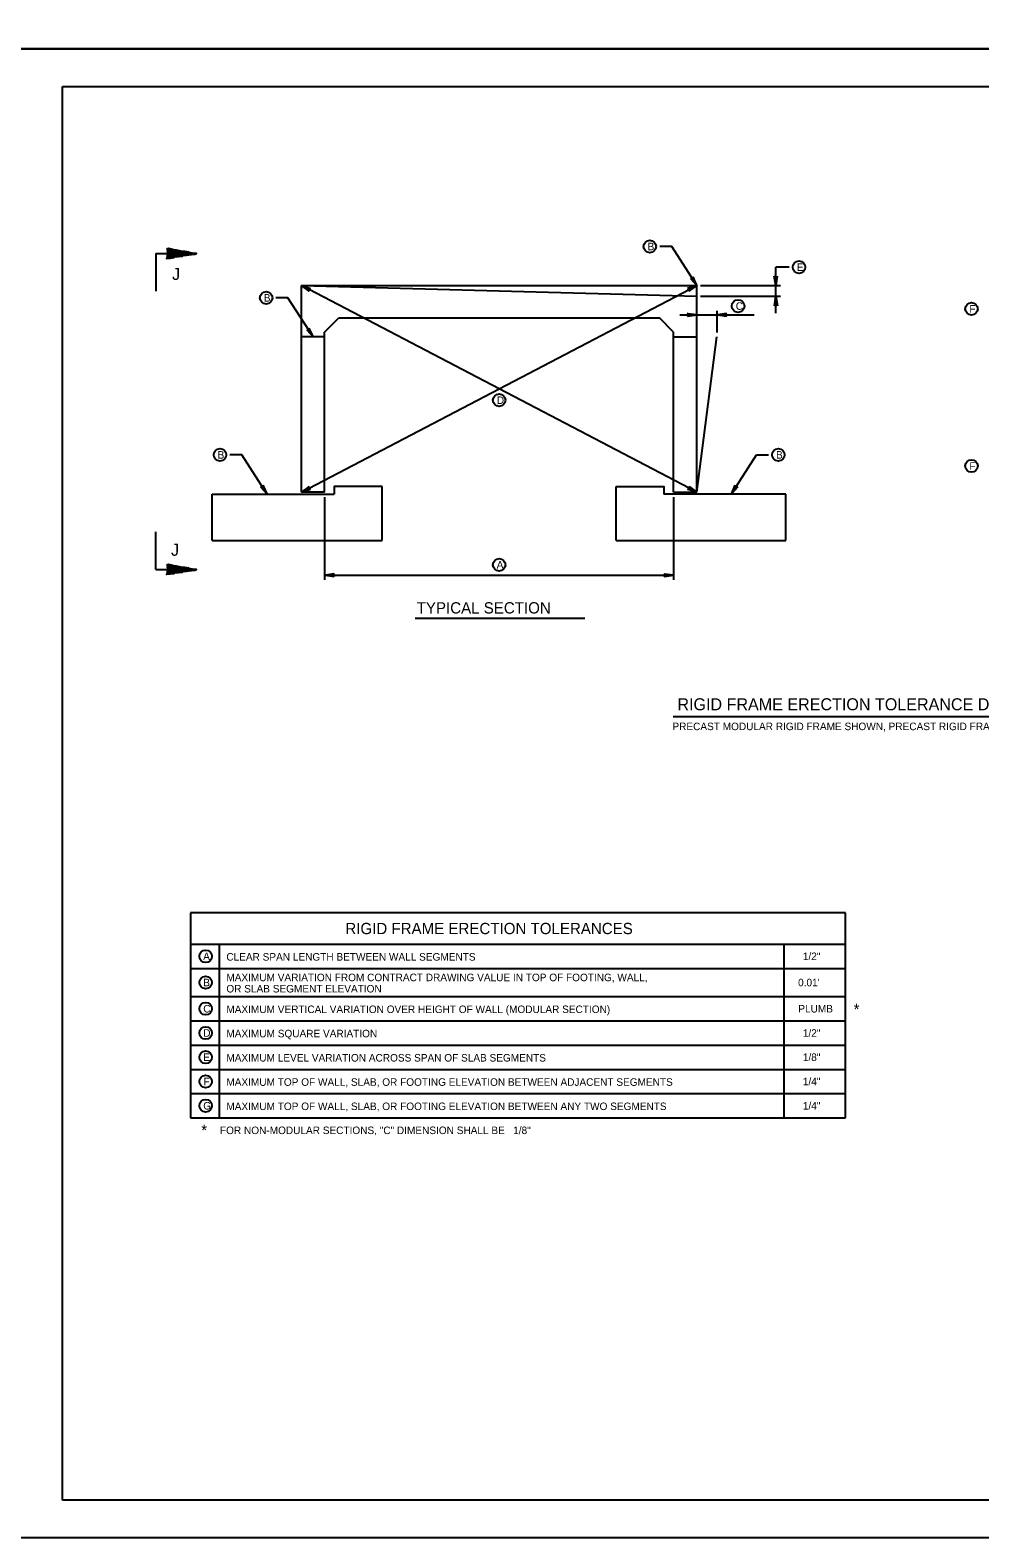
# Model space of a CAD drawing. Extents: x 641328 to 643024, y 298283 to 300065.
# Drawn here: x 642196 to 642575, y 298283 to 298885 of the extents above; entities that cross this region are included whole.
import ezdxf

# ---------------------------------------------------------------- set-up
doc = ezdxf.new("R2010")
doc.units = 0
doc.layers.add('2', color=7, linetype='Continuous')
doc.layers.add('PLT-BNDY', color=7, linetype='Continuous')

msp = doc.modelspace()

# ---------------------------------------------------------------- linework, layer by layer
at = {"layer": '2'}
for p, q in [((642208.51, 298298.3), (642208.51, 298862.3)), ((642208.51, 298862.3), (642994.5, 298862.3)), ((642245.76, 298795.71), (642245.76, 298780.68)), ((642245.76, 298795.71), (642260.79, 298795.71)), ((642451.59, 298798.49), (642446.77, 298798.49)), ((642461.6, 298782.89), (642451.59, 298798.49)), ((642493.12, 298771.84), (642493.12, 298790.22)), ((642498.42, 298790.22), (642493.12, 298790.22)), ((642459.29, 298785.69), (642459.05, 298785.77)), ((642459.05, 298785.77), (642461.6, 298782.89)), ((642459.29, 298785.69), (642459.59, 298785.72)), ((642461.6, 298782.89), (642459.29, 298785.69)), ((642459.59, 298785.72), (642459.89, 298785.91)), ((642459.59, 298785.72), (642461.6, 298782.89)), ((642461.6, 298782.89), (642459.74, 298785.82)), ((642459.89, 298785.91), (642460.04, 298786.16)), ((642461.6, 298782.89), (642459.89, 298785.91)), ((642460.09, 298786.42), (642460.04, 298786.16)), ((642460.04, 298786.16), (642461.6, 298782.89)), ((642461.6, 298782.89), (642460.09, 298786.42)), ((642493.12, 298782.89), (642492.49, 298786.68)), ((642492.49, 298786.68), (642492.66, 298786.48)), ((642492.92, 298786.36), (642492.66, 298786.48)), ((642492.66, 298786.48), (642493.12, 298782.89)), ((642493.12, 298782.89), (642492.92, 298786.36)), ((642493.29, 298786.36), (642492.92, 298786.36)), ((642493.12, 298782.89), (642493.1, 298786.36)), ((642493.71, 298786.69), (642493.12, 298782.89)), ((642493.12, 298782.89), (642493.55, 298786.5)), ((642493.29, 298786.36), (642493.12, 298782.89)), ((642493.55, 298786.5), (642493.29, 298786.36)), ((642493.55, 298786.5), (642493.71, 298786.69)), ((642298.49, 298777.99), (642293.67, 298777.99)), ((642308.5, 298762.39), (642298.49, 298777.99)), ((642303.85, 298782.89), (642461.6, 298782.89)), ((642303.85, 298700.46), (642303.85, 298782.89)), ((642303.85, 298700.46), (642461.6, 298782.89)), ((642461.6, 298700.46), (642303.85, 298782.89)), ((642306.85, 298781.13), (642303.85, 298782.89)), ((642303.85, 298782.89), (642306.85, 298780.83)), ((642306.95, 298780.6), (642303.85, 298782.89)), ((642303.85, 298782.89), (642307.02, 298781.45)), ((642307.25, 298781.63), (642303.85, 298782.89)), ((642303.85, 298782.89), (642307.51, 298781.69)), ((642303.85, 298782.89), (642306.94, 298781.29)), ((642303.85, 298782.89), (642461.6, 298778.63)), ((642306.85, 298781.13), (642307.02, 298781.45)), ((642306.85, 298780.83), (642306.85, 298781.13)), ((642306.85, 298780.83), (642306.95, 298780.6)), ((642307.02, 298781.45), (642307.25, 298781.63)), ((642307.51, 298781.69), (642307.25, 298781.63)), ((642461.6, 298782.89), (642457.94, 298781.69)), ((642457.94, 298781.69), (642458.2, 298781.63)), ((642458.2, 298781.63), (642461.6, 298782.89)), ((642458.43, 298781.45), (642458.2, 298781.63)), ((642461.6, 298782.89), (642458.43, 298781.45)), ((642458.6, 298781.13), (642458.43, 298781.45)), ((642458.5, 298780.6), (642461.6, 298782.89)), ((642458.6, 298780.83), (642458.5, 298780.6)), ((642461.6, 298782.89), (642458.52, 298781.29)), ((642458.6, 298781.13), (642461.6, 298782.89)), ((642461.6, 298782.89), (642458.6, 298780.83)), ((642458.6, 298780.83), (642458.6, 298781.13)), ((642461.6, 298700.46), (642461.6, 298782.89)), ((642463.1, 298782.89), (642494.94, 298782.89)), ((642463.1, 298778.63), (642494.94, 298778.63)), ((642492.53, 298774.83), (642493.12, 298778.63)), ((642493.12, 298778.63), (642492.69, 298775.02)), ((642492.95, 298775.16), (642493.12, 298778.63)), ((642493.12, 298778.63), (642493.32, 298775.16)), ((642493.58, 298775.03), (642493.12, 298778.63)), ((642493.12, 298778.63), (642493.75, 298774.84)), ((642493.12, 298778.63), (642493.14, 298775.16)), ((642457.99, 298771.62), (642457.8, 298771.78)), ((642457.8, 298771.78), (642461.6, 298771.19)), ((642457.99, 298771.62), (642458.13, 298771.36)), ((642461.6, 298771.19), (642457.99, 298771.62)), ((642458.13, 298771.36), (642461.6, 298771.19)), ((642458.13, 298771.36), (642458.13, 298771)), ((642469.62, 298772.79), (642469.62, 298764.13)), ((642469.62, 298771.19), (642473.42, 298771.83)), ((642473.22, 298771.65), (642469.62, 298771.19)), ((642469.62, 298771.19), (642473.09, 298771.39)), ((642473.09, 298771.39), (642473.22, 298771.65)), ((642473.1, 298771.03), (642473.09, 298771.39)), ((642473.42, 298771.83), (642473.22, 298771.65)), ((642492.69, 298775.02), (642492.53, 298774.83)), ((642492.69, 298775.02), (642492.95, 298775.16)), ((642492.95, 298775.16), (642493.32, 298775.16)), ((642493.32, 298775.16), (642493.58, 298775.03)), ((642493.75, 298774.84), (642493.58, 298775.03)), ((642306.48, 298765.23), (642306.79, 298765.42)), ((642306.79, 298765.42), (642306.94, 298765.67)), ((642308.5, 298762.39), (642306.79, 298765.42)), ((642306.98, 298765.93), (642306.94, 298765.67)), ((642306.94, 298765.67), (642308.5, 298762.39)), ((642308.5, 298762.39), (642306.98, 298765.93)), ((642313.1, 298764.3), (642318.82, 298770.01)), ((642318.82, 298770.01), (642446.66, 298770.01)), ((642452.35, 298764.32), (642446.66, 298770.01)), ((642454.83, 298771.19), (642484.43, 298771.19)), ((642461.6, 298771.19), (642457.81, 298770.56)), ((642457.81, 298770.56), (642458, 298770.74)), ((642458, 298770.74), (642461.6, 298771.19)), ((642458.13, 298771), (642458, 298770.74)), ((642461.6, 298771.19), (642458.13, 298771)), ((642461.6, 298771.19), (642458.13, 298771.18)), ((642469.62, 298771.19), (642473.1, 298771.21)), ((642473.1, 298771.03), (642469.62, 298771.19)), ((642469.62, 298771.19), (642473.23, 298770.76)), ((642473.42, 298770.6), (642469.62, 298771.19)), ((642473.23, 298770.76), (642473.1, 298771.03)), ((642473.23, 298770.76), (642473.42, 298770.6)), ((642313.12, 298762.39), (642303.87, 298762.39)), ((642306.19, 298765.2), (642305.95, 298765.27)), ((642305.95, 298765.27), (642308.5, 298762.39)), ((642306.19, 298765.2), (642306.48, 298765.23)), ((642308.5, 298762.39), (642306.19, 298765.2)), ((642306.48, 298765.23), (642308.5, 298762.39)), ((642308.5, 298762.39), (642306.64, 298765.32)), ((642313.1, 298700.46), (642313.1, 298764.3)), ((642452.35, 298700.46), (642452.35, 298764.32)), ((642452.35, 298762.39), (642461.6, 298762.39)), ((642461.6, 298700.46), (642469.62, 298762.39)), ((642280.08, 298715.35), (642275.26, 298715.35)), ((642290.09, 298699.75), (642280.08, 298715.35)), ((642475.39, 298699.75), (642485.39, 298715.35)), ((642485.39, 298715.35), (642490.21, 298715.35)), ((642268.3, 298681.21), (642268.3, 298699.71)), ((642268.3, 298699.71), (642316.96, 298699.71)), ((642287.78, 298702.56), (642287.54, 298702.63)), ((642287.54, 298702.63), (642290.09, 298699.75)), ((642287.78, 298702.56), (642288.07, 298702.59)), ((642290.09, 298699.75), (642287.78, 298702.56)), ((642288.07, 298702.59), (642288.38, 298702.78)), ((642288.07, 298702.59), (642290.09, 298699.75)), ((642290.09, 298699.75), (642288.23, 298702.68)), ((642288.38, 298702.78), (642288.53, 298703.03)), ((642290.09, 298699.75), (642288.38, 298702.78)), ((642288.57, 298703.29), (642288.53, 298703.03)), ((642288.53, 298703.03), (642290.09, 298699.75)), ((642290.09, 298699.75), (642288.57, 298703.29)), ((642306.95, 298702.74), (642303.85, 298700.46)), ((642303.85, 298700.46), (642306.85, 298702.51)), ((642306.85, 298702.21), (642303.85, 298700.46)), ((642303.85, 298700.46), (642306.94, 298702.05)), ((642303.85, 298700.46), (642307.02, 298701.89)), ((642307.25, 298701.72), (642303.85, 298700.46)), ((642303.85, 298700.46), (642307.51, 298701.65)), ((642306.85, 298702.51), (642306.95, 298702.74)), ((642306.85, 298702.51), (642306.85, 298702.21)), ((642306.85, 298702.21), (642307.02, 298701.89)), ((642307.02, 298701.89), (642307.25, 298701.72)), ((642307.51, 298701.65), (642307.25, 298701.72)), ((642336.1, 298681.21), (642336.1, 298702.71)), ((642429.35, 298681.21), (642429.35, 298702.71)), ((642497.15, 298699.71), (642448.49, 298699.71)), ((642457.94, 298701.65), (642458.2, 298701.72)), ((642461.6, 298700.46), (642457.94, 298701.65)), ((642458.43, 298701.89), (642458.2, 298701.72)), ((642458.2, 298701.72), (642461.6, 298700.46)), ((642458.6, 298702.21), (642458.43, 298701.89)), ((642461.6, 298700.46), (642458.43, 298701.89)), ((642458.6, 298702.51), (642458.5, 298702.74)), ((642458.5, 298702.74), (642461.6, 298700.46)), ((642461.6, 298700.46), (642458.52, 298702.05)), ((642458.6, 298702.51), (642458.6, 298702.21)), ((642461.6, 298700.46), (642458.6, 298702.51)), ((642458.6, 298702.21), (642461.6, 298700.46)), ((642475.39, 298699.75), (642476.9, 298703.29)), ((642476.94, 298703.03), (642475.39, 298699.75)), ((642475.39, 298699.75), (642477.1, 298702.78)), ((642475.39, 298699.75), (642477.25, 298702.68)), ((642477.94, 298702.63), (642475.39, 298699.75)), ((642477.4, 298702.59), (642475.39, 298699.75)), ((642475.39, 298699.75), (642477.7, 298702.56)), ((642476.9, 298703.29), (642476.94, 298703.03)), ((642477.1, 298702.78), (642476.94, 298703.03)), ((642477.4, 298702.59), (642477.1, 298702.78)), ((642477.7, 298702.56), (642477.4, 298702.59)), ((642477.7, 298702.56), (642477.94, 298702.63)), ((642497.15, 298681.21), (642497.15, 298699.71)), ((642313.1, 298698.53), (642313.1, 298665.44)), ((642452.35, 298698.53), (642452.35, 298665.44)), ((642245.76, 298669.56), (642245.76, 298684.59)), ((642268.3, 298681.21), (642336.1, 298681.21)), ((642429.35, 298681.21), (642497.15, 298681.21)), ((642245.76, 298669.56), (642260.79, 298669.56)), ((642313.1, 298667.35), (642316.89, 298667.99)), ((642316.7, 298667.81), (642313.1, 298667.35)), ((642313.1, 298667.35), (642316.57, 298667.55)), ((642313.1, 298667.35), (642316.57, 298667.37)), ((642313.1, 298667.35), (642452.35, 298667.35)), ((642316.57, 298667.18), (642313.1, 298667.35)), ((642313.1, 298667.35), (642316.71, 298666.92)), ((642316.9, 298666.76), (642313.1, 298667.35)), ((642316.57, 298667.55), (642316.7, 298667.81)), ((642316.57, 298667.18), (642316.57, 298667.55)), ((642316.71, 298666.92), (642316.57, 298667.18)), ((642316.89, 298667.99), (642316.7, 298667.81)), ((642316.71, 298666.92), (642316.9, 298666.76)), ((642448.74, 298667.78), (642448.55, 298667.94)), ((642448.55, 298667.94), (642452.35, 298667.35)), ((642452.35, 298667.35), (642448.56, 298666.72)), ((642448.56, 298666.72), (642448.75, 298666.89)), ((642448.74, 298667.78), (642448.88, 298667.52)), ((642452.35, 298667.35), (642448.74, 298667.78)), ((642448.75, 298666.89), (642452.35, 298667.35)), ((642448.88, 298667.15), (642448.75, 298666.89)), ((642448.88, 298667.52), (642452.35, 298667.35)), ((642448.88, 298667.52), (642448.88, 298667.15)), ((642452.35, 298667.35), (642448.88, 298667.15)), ((642452.35, 298667.35), (642448.88, 298667.34)), ((642349.23, 298650.25), (642416.98, 298650.25)), ((642452.2, 298610.98), (642636.88, 298610.98)), ((642259.63, 298520.15), (642520.87, 298520.15)), ((642271.02, 298520.15), (642271.02, 298450.85)), ((642496.27, 298520.15), (642496.27, 298450.85)), ((642259.63, 298510.47), (642520.87, 298510.47)), ((642259.63, 298510.47), (642259.63, 298499.23)), ((642259.63, 298499.23), (642520.87, 298499.23)), ((642259.63, 298489.55), (642520.87, 298489.55)), ((642259.63, 298479.88), (642520.87, 298479.88)), ((642259.63, 298470.2), (642520.87, 298470.2)), ((642259.63, 298460.52), (642520.87, 298460.52)), ((642994.5, 298298.3), (642208.51, 298298.3))]:
    msp.add_line(p, q, dxfattribs=at)
for points in [[(642250.06, 298797.63), (642261.94, 298795.65), (642250.06, 298793.67), (642250.26, 298793.87), (642251.44, 298793.87), (642253.03, 298794.07), (642250.26, 298794.07), (642250.45, 298794.47), (642254.81, 298794.47), (642256.39, 298794.66), (642250.45, 298794.66), (642250.45, 298795.06), (642257.98, 298795.06), (642259.96, 298795.26), (642250.45, 298795.26), (642250.45, 298795.46), (642261.34, 298795.46), (642261.94, 298795.65), (642260.35, 298795.85), (642250.65, 298795.85), (642250.45, 298796.05), (642258.97, 298796.25), (642257.38, 298796.45), (642250.45, 298796.45), (642250.45, 298796.64), (642255.8, 298796.64), (642254.02, 298797.04), (642250.45, 298797.04), (642250.26, 298797.24), (642252.63, 298797.24), (642250.85, 298797.63), (642250.26, 298797.44)], [(642313.1, 298700.46), (642303.85, 298700.46)], [(642336.1, 298702.71), (642316.96, 298702.71), (642316.96, 298699.71)], [(642429.35, 298702.71), (642448.49, 298702.71), (642448.49, 298699.71)], [(642452.35, 298700.46), (642461.6, 298700.46)], [(642250.06, 298671.59), (642261.94, 298669.61), (642250.06, 298667.63), (642250.26, 298667.83), (642251.44, 298667.83), (642253.03, 298668.03), (642250.26, 298668.03), (642250.45, 298668.43), (642254.81, 298668.43), (642256.39, 298668.62), (642250.45, 298668.62), (642250.45, 298669.02), (642257.98, 298669.02), (642259.96, 298669.22), (642250.45, 298669.22), (642250.45, 298669.42), (642261.34, 298669.42), (642261.94, 298669.61), (642260.35, 298669.81), (642250.65, 298669.81), (642250.45, 298670.01), (642258.97, 298670.21), (642257.38, 298670.41), (642250.45, 298670.41), (642250.45, 298670.6), (642255.8, 298670.6), (642254.02, 298671), (642250.45, 298671), (642250.26, 298671.2), (642252.63, 298671.2), (642250.85, 298671.59), (642250.26, 298671.4)], [(642259.63, 298532.65), (642259.63, 298450.85)], [(642520.87, 298532.65), (642259.63, 298532.65)], [(642520.87, 298450.85), (642520.87, 298532.65)], [(642259.63, 298450.85), (642520.87, 298450.85)]]:
    msp.add_lwpolyline(points, dxfattribs=at)
for centre in [(642442.86, 298798.49), (642502.38, 298790.22), (642289.76, 298777.99), (642478.06, 298774.72), (642571.19, 298773.62), (642382.73, 298737.16), (642271.35, 298715.35), (642494.13, 298715.35), (642571.19, 298710.93), (642382.73, 298671.49), (642265.62, 298515.31), (642265.62, 298504.85), (642265.62, 298494.39), (642265.62, 298484.71), (642265.62, 298475.04), (642265.62, 298465.36), (642265.62, 298455.68)]:
    msp.add_circle(centre, 2.5, dxfattribs=at)
at = {"layer": 'PLT-BNDY'}
for points in [[(642168.51, 299471.3), (643009.51, 299471.3), (643009.51, 298877.3), (642168.51, 298877.3)], [(642168.51, 298877.3), (643009.51, 298877.3), (643009.51, 298283.3), (642168.51, 298283.3)]]:
    msp.add_lwpolyline(points, close=True, dxfattribs=at)

# ---------------------------------------------------------------- texts
at = {"layer": '2'}
for s, height, p in [('B', 3, (642441.93, 298796.99)), ('J', 4.8, (642252.26, 298785.14)), ('E', 3, (642501.46, 298788.72)), ('B', 3, (642288.82, 298776.49)), ('C', 3, (642477.13, 298773.22)), ('F', 3, (642570.33, 298772.12)), ('D', 3, (642381.79, 298735.66)), ('B', 3, (642270.41, 298713.85)), ('B', 3, (642493.2, 298713.85)), ('F', 3, (642570.33, 298709.43)), ('J', 4.8, (642251.81, 298675.09)), ('A', 3, (642381.75, 298669.99)), ('TYPICAL SECTION', 4.5, (642349.83, 298652.07)), ('RIGID FRAME ERECTION TOLERANCE DETAILS', 4.8, (642453.85, 298613.45)), ('PRECAST MODULAR RIGID FRAME SHOWN, PRECAST RIGID FRAME SIMILAR.', 3, (642451.86, 298605.53)), ('RIGID FRAME ERECTION TOLERANCES', 4.5, (642321.37, 298524.15)), ('A', 3, (642264.64, 298513.81)), ('CLEAR SPAN LENGTH BETWEEN WALL SEGMENTS', 3, (642273.9, 298513.59)), ('  1/2"', 3, (642501.66, 298513.81)), ('MAXIMUM VARIATION FROM CONTRACT DRAWING VALUE IN TOP OF FOOTING, WALL, ', 3, (642273.9, 298505.38)), ('B', 3, (642264.69, 298503.35)), ('OR SLAB SEGMENT ELEVATION', 3, (642273.9, 298500.88)), ("  0.01'", 3, (642499.77, 298503.35)), ('C', 3, (642264.69, 298492.89)), ('MAXIMUM VERTICAL VARIATION OVER HEIGHT OF WALL (MODULAR SECTION)', 3, (642273.9, 298492.67)), ('PLUMB', 3, (642502.08, 298492.89)), ('*', 4.5, (642524.15, 298491.89)), ('D', 3, (642264.69, 298483.21)), ('MAXIMUM SQUARE VARIATION', 3, (642273.9, 298482.99)), ('  1/2"', 3, (642501.66, 298483.21)), ('  1/8"', 3, (642501.66, 298473.54)), ('E', 3, (642264.7, 298473.54)), ('MAXIMUM LEVEL VARIATION ACROSS SPAN OF SLAB SEGMENTS', 3, (642273.9, 298473.32)), ('F', 3, (642264.76, 298463.86)), ('MAXIMUM TOP OF WALL, SLAB, OR FOOTING ELEVATION BETWEEN ADJACENT SEGMENTS', 3, (642273.9, 298463.64)), ('  1/4"', 3, (642501.66, 298463.86)), ('G', 3, (642264.69, 298454.18)), ('MAXIMUM TOP OF WALL, SLAB, OR FOOTING ELEVATION BETWEEN ANY TWO SEGMENTS', 3, (642273.9, 298453.96)), ('  1/4"', 3, (642501.66, 298454.18)), ('*', 4.5, (642263.89, 298443.63)), ('FOR NON-MODULAR SECTIONS, "C" DIMENSION SHALL BE   1/8"', 3, (642271.35, 298444.38))]:
    msp.add_text(s, height=height, dxfattribs=at).set_placement(p)

doc.saveas('drawing.dxf')
